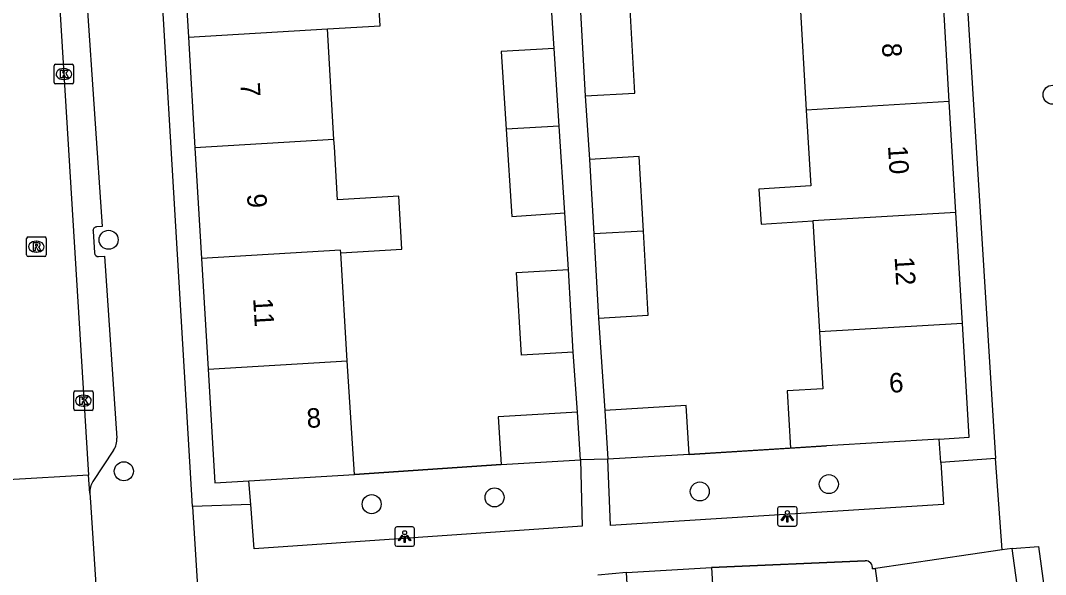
# Model space of a CAD drawing. Extents: x 159053 to 160041, y 380450 to 381422.
# Drawn here: x 159617.1 to 159669.8, y 381129.1 to 381157.6 of the extents above; entities that cross this region are included whole.
import ezdxf

# ---------------------------------------------------------------- set-up
doc = ezdxf.new("R2010")
doc.units = 0
for name, color, linetype in [('IMGEO_Boom', 7, 'Continuous'), ('IMGEO_Groenvoorziening', 7, 'Continuous'), ('IMGEO_Kolk', 7, 'Continuous'), ('IMGEO_Lichtpunt', 7, 'Continuous'), ('IMGEO_Muur', 7, 'Continuous'), ('IMGEO_Pand', 7, 'Continuous'), ('IMGEO_Pand_nummerreeks', 7, 'Continuous'), ('IMGEO_Rijbaan_lokaal_open', 7, 'Continuous'), ('IMGEO_Rioolput', 7, 'Continuous'), ('IMGEO_Voetpad_open', 7, 'Continuous')]:
    doc.layers.add(name, color=color, linetype=linetype)

msp = doc.modelspace()

# ---------------------------------------------------------------- linework, layer by layer
at = {"layer": 'IMGEO_Boom'}
for centre in [(159670.128, 381153.776), (159621.666, 381146.323), (159622.448, 381134.43), (159658.638, 381133.772), (159652.014, 381133.396), (159635.17, 381132.742), (159641.478, 381133.09)]:
    msp.add_circle(centre, 0.489, dxfattribs=at)
at = {"layer": 'IMGEO_Groenvoorziening'}
for points in [[(159664.387, 381134.882), (159664.307, 381136.089)], [(159656.669, 381135.627), (159651.462, 381135.295)], [(159634.284, 381134.272), (159641.811, 381134.775)], [(159628.96, 381132.732), (159628.867, 381133.949)]]:
    msp.add_lwpolyline(points, dxfattribs=at)
at = {"layer": 'IMGEO_Kolk'}
for p, q in [((159618.945, 381155.337), (159619.797, 381155.337)), ((159618.87, 381154.411), (159618.87, 381155.263)), ((159619.358, 381155.117), (159619.383, 381155.117)), ((159619.871, 381155.263), (159619.871, 381154.411)), ((159619.797, 381154.337), (159618.945, 381154.337)), ((159619.381, 381154.557), (159619.356, 381154.557)), ((159619.873, 381137.634), (159619.873, 381138.486)), ((159619.948, 381138.56), (159620.8, 381138.56)), ((159620.874, 381138.486), (159620.874, 381137.634)), ((159620.361, 381138.34), (159620.386, 381138.34)), ((159620.8, 381137.56), (159619.948, 381137.56)), ((159620.384, 381137.78), (159620.359, 381137.78))]:
    msp.add_line(p, q, dxfattribs=at)
for points in [[(159618.945, 381155.337), (159619.797, 381155.337)], [(159618.87, 381154.411), (159618.87, 381155.263)], [(159619.191, 381155.037), (159619.314, 381155.037), (159619.314, 381154.886), (159619.444, 381155.037), (159619.608, 381155.037), (159619.462, 381154.886), (159619.615, 381154.637), (159619.463, 381154.637), (159619.378, 381154.801), (159619.314, 381154.734), (159619.314, 381154.637), (159619.191, 381154.637), (159619.191, 381155.037)], [(159619.871, 381155.263), (159619.871, 381154.411)], [(159619.797, 381154.337), (159618.945, 381154.337)], [(159619.873, 381137.634), (159619.873, 381138.486)], [(159619.948, 381138.56), (159620.8, 381138.56)], [(159620.874, 381138.486), (159620.874, 381137.634)], [(159620.194, 381138.26), (159620.317, 381138.26), (159620.317, 381138.109), (159620.447, 381138.26), (159620.611, 381138.26), (159620.465, 381138.109), (159620.618, 381137.86), (159620.466, 381137.86), (159620.381, 381138.024), (159620.317, 381137.957), (159620.317, 381137.86), (159620.194, 381137.86), (159620.194, 381138.26)], [(159620.8, 381137.56), (159619.948, 381137.56)]]:
    msp.add_lwpolyline(points, dxfattribs=at)
for centre, start, end in [((159618.947, 381155.261), 91.552, 178.448), ((159618.947, 381155.261), 91.552, 178.448), ((159619.795, 381155.261), 1.552, 88.448), ((159619.795, 381155.261), 1.552, 88.448), ((159618.947, 381154.413), 181.552, 268.448), ((159618.947, 381154.413), 181.552, 268.448), ((159619.795, 381154.413), 271.552, 358.448), ((159619.795, 381154.413), 271.552, 358.448), ((159619.95, 381138.484), 91.552, 178.448), ((159619.95, 381138.484), 91.552, 178.448), ((159620.798, 381138.484), 1.552, 88.448), ((159620.798, 381138.484), 1.552, 88.448), ((159619.95, 381137.636), 181.552, 268.448), ((159619.95, 381137.636), 181.552, 268.448), ((159620.798, 381137.636), 271.552, 358.448), ((159620.798, 381137.636), 271.552, 358.448)]:
    msp.add_arc(centre, 0.0765, start, end, dxfattribs=at)
for centre, major_axis, ratio, start_param, end_param in [((159619.357, 381154.837), (-0.387, 0.002), 0.722429, 4.712389, 7.853982), ((159619.382, 381154.837), (-0.39, 0.002), 0.717154, 1.570796, 4.712389), ((159620.36, 381138.06), (-0.387, 0.002), 0.722429, 4.712389, 7.853982), ((159620.385, 381138.06), (-0.39, 0.002), 0.717154, 1.570796, 4.712389)]:
    msp.add_ellipse(centre, major_axis=major_axis, ratio=ratio, start_param=start_param, end_param=end_param, dxfattribs=at)
at = {"layer": 'IMGEO_Lichtpunt'}
for p, q in [((159656.01, 381132.519), (159656.01, 381131.712)), ((159656.01, 381132.519), (159656.01, 381131.712)), ((159656.912, 381132.614), (159656.104, 381132.614)), ((159656.912, 381132.614), (159656.104, 381132.614)), ((159657.006, 381131.712), (159657.006, 381132.519)), ((159657.006, 381131.712), (159657.006, 381132.519)), ((159636.365, 381131.479), (159636.365, 381130.672)), ((159636.365, 381131.479), (159636.365, 381130.672)), ((159637.267, 381131.574), (159636.459, 381131.574)), ((159637.267, 381131.574), (159636.459, 381131.574)), ((159637.361, 381130.672), (159637.361, 381131.479)), ((159637.361, 381130.672), (159637.361, 381131.479)), ((159656.104, 381131.618), (159656.912, 381131.618)), ((159656.104, 381131.618), (159656.912, 381131.618)), ((159636.459, 381130.578), (159637.267, 381130.578)), ((159636.459, 381130.578), (159637.267, 381130.578))]:
    msp.add_line(p, q, dxfattribs=at)
for points in [[(159656.384, 381132.183), (159656.423, 381132.155), (159656.235, 381131.893), (159656.197, 381131.92), (159656.384, 381132.183)], [(159656.596, 381132.155), (159656.634, 381132.182), (159656.821, 381131.92), (159656.782, 381131.892), (159656.596, 381132.155)], [(159656.486, 381132.135), (159656.533, 381132.135), (159656.533, 381131.813), (159656.486, 381131.813), (159656.486, 381132.135)], [(159636.739, 381131.143), (159636.778, 381131.115), (159636.59, 381130.853), (159636.552, 381130.88), (159636.739, 381131.143)], [(159636.951, 381131.115), (159636.989, 381131.142), (159637.176, 381130.88), (159637.137, 381130.852), (159636.951, 381131.115)], [(159636.841, 381131.095), (159636.888, 381131.095), (159636.888, 381130.773), (159636.841, 381130.773), (159636.841, 381131.095)]]:
    msp.add_lwpolyline(points, dxfattribs=at)
for centre in [(159656.509, 381132.317), (159636.864, 381131.277)]:
    msp.add_circle(centre, 0.0994, dxfattribs=at)
for centre, start, end in [((159656.104, 381132.519), 90, 180), ((159656.104, 381132.519), 90, 180), ((159656.912, 381132.519), 0, 90), ((159656.912, 381132.519), 0, 90), ((159656.104, 381131.712), 180, 270), ((159656.104, 381131.712), 180, 270), ((159656.912, 381131.712), 270, 0), ((159656.912, 381131.712), 270, 360), ((159636.459, 381131.479), 90, 180), ((159636.459, 381131.479), 90, 180), ((159637.267, 381131.479), 0, 90), ((159637.267, 381131.479), 0, 90), ((159636.459, 381130.672), 180, 270), ((159636.459, 381130.672), 180, 270), ((159637.267, 381130.672), 270, 0), ((159637.267, 381130.672), 270, 360)]:
    msp.add_arc(centre, 0.0946, start, end, dxfattribs=at)
at = {"layer": 'IMGEO_Muur'}
for points in [[(159651.462, 381135.295), (159658.51, 381135.744)], [(159641.811, 381134.775), (159634.284, 381134.272)], [(159652.616, 381129.495), (159660.501, 381129.836)], [(159660.884, 381129.414), (159661.027, 381129.435)]]:
    msp.add_lwpolyline(points, dxfattribs=at)
msp.add_arc((159660.515, 381129.464), 0.372, 352.2658, 92.1869, dxfattribs=at)
at = {"layer": 'IMGEO_Pand'}
for points in [[(159632.896, 381157.16), (159635.606, 381157.321), (159635.267, 381163.006), (159632.557, 381162.845)], [(159625.422, 381162.42), (159625.761, 381156.735)], [(159664.823, 381153.421), (159664.484, 381159.118)], [(159657.144, 381158.683), (159657.483, 381152.986)], [(159645.89, 381158.016), (159646.131, 381153.714)], [(159646.131, 381153.714), (159648.687, 381153.857), (159648.446, 381158.168)], [(159625.761, 381156.735), (159632.896, 381157.16)], [(159633.235, 381151.475), (159632.896, 381157.16)], [(159625.761, 381156.735), (159626.1, 381151.05)], [(159644.535, 381156.153), (159641.823, 381155.991), (159642.079, 381152.002)], [(159644.792, 381152.163), (159644.535, 381156.153)], [(159664.823, 381153.421), (159657.483, 381152.986)], [(159665.162, 381147.724), (159664.823, 381153.421)], [(159657.483, 381152.986), (159657.715, 381149.088), (159655.053, 381148.93), (159655.16, 381147.131), (159657.823, 381147.289)], [(159644.792, 381152.163), (159642.079, 381152.002)], [(159645.079, 381147.7), (159644.792, 381152.163)], [(159642.079, 381152.002), (159642.368, 381147.525), (159645.079, 381147.7)], [(159633.235, 381151.475), (159626.1, 381151.05)], [(159633.581, 381145.657), (159636.725, 381145.845), (159636.564, 381148.567), (159633.419, 381148.38), (159633.257, 381151.103), (159633.235, 381151.475)], [(159626.1, 381151.05), (159626.439, 381145.365)], [(159649.123, 381146.773), (159648.91, 381150.595), (159646.353, 381150.452)], [(159646.353, 381150.452), (159646.568, 381146.622)], [(159665.162, 381147.724), (159657.823, 381147.289)], [(159665.502, 381142.027), (159665.162, 381147.724)], [(159657.823, 381147.289), (159658.162, 381141.592)], [(159649.123, 381146.773), (159646.568, 381146.622)], [(159646.568, 381146.622), (159646.809, 381142.305)], [(159646.809, 381142.305), (159649.365, 381142.448), (159649.123, 381146.773)], [(159633.581, 381145.657), (159633.573, 381145.79), (159626.439, 381145.365)], [(159626.439, 381145.365), (159626.777, 381139.68)], [(159633.912, 381140.105), (159633.581, 381145.657)], [(159645.519, 381140.557), (159642.854, 381140.398), (159642.602, 381144.635), (159645.267, 381144.793)], [(159645.519, 381140.557), (159645.267, 381144.793)], [(159665.502, 381142.027), (159658.162, 381141.592)], [(159664.307, 381136.089), (159665.85, 381136.181), (159665.502, 381142.027)], [(159658.162, 381141.592), (159658.336, 381138.668), (159656.495, 381138.558), (159656.669, 381135.627)], [(159626.777, 381139.68), (159633.912, 381140.105)], [(159634.284, 381134.272), (159633.912, 381140.105)], [(159626.777, 381139.68), (159627.125, 381133.845), (159628.867, 381133.949)], [(159645.738, 381137.468), (159641.665, 381137.225), (159641.811, 381134.775)], [(159645.885, 381135.017), (159645.738, 381137.468)], [(159651.462, 381135.295), (159651.313, 381137.804), (159647.136, 381137.555)], [(159647.136, 381137.555), (159647.285, 381135.046)], [(159664.307, 381136.089), (159658.51, 381135.744), (159656.669, 381135.627)], [(159641.811, 381134.775), (159645.885, 381135.017)], [(159651.462, 381135.295), (159647.285, 381135.046)], [(159628.867, 381133.949), (159634.284, 381134.272)], [(159667.53, 381130.39), (159661.027, 381129.435)], [(159668.05, 381130.466), (159667.53, 381130.39)], [(159668.849, 381124.614), (159668.05, 381130.466)], [(159648.258, 381129.236), (159652.616, 381129.495)], [(159648.414, 381126.627), (159648.258, 381129.236)], [(159652.616, 381129.495), (159652.772, 381126.886), (159648.414, 381126.627)], [(159661.826, 381123.579), (159661.703, 381124.481), (159661.027, 381129.435)]]:
    msp.add_lwpolyline(points, dxfattribs=at)
at = {"layer": 'IMGEO_Rijbaan_lokaal_open'}
for points in [[(159618.267, 381172.995), (159618.959, 381161.536), (159620.639, 381134.237)], [(159620.639, 381134.237), (159616.518, 381133.993)], [(159620.696, 381133.307), (159620.639, 381134.237)], [(159620.696, 381133.307), (159620.73, 381132.839), (159621.044, 381128.068), (159621.135, 381127.424)]]:
    msp.add_lwpolyline(points, dxfattribs=at)
at = {"layer": 'IMGEO_Rioolput'}
for p, q in [((159617.459, 381145.542), (159617.459, 381146.394)), ((159617.534, 381146.468), (159618.386, 381146.468)), ((159618.46, 381146.394), (159618.46, 381145.542)), ((159617.947, 381146.248), (159617.972, 381146.248)), ((159618.386, 381145.468), (159617.534, 381145.468)), ((159617.97, 381145.688), (159617.945, 381145.688))]:
    msp.add_line(p, q, dxfattribs=at)
for points in [[(159617.459, 381145.542), (159617.459, 381146.394)], [(159617.534, 381146.468), (159618.386, 381146.468)], [(159618.46, 381146.394), (159618.46, 381145.542)], [(159618.048, 381146.166), (159617.796, 381146.168), (159617.796, 381145.768)], [(159617.796, 381145.768), (159617.92, 381145.768), (159617.92, 381145.93), (159617.931, 381145.93)], [(159617.974, 381146.087), (159617.92, 381146.087), (159617.92, 381146.006)], [(159617.92, 381146.006), (159617.972, 381146.006)], [(159617.978, 381145.901), (159618.049, 381145.768), (159618.189, 381145.768), (159618.124, 381145.894)], [(159618.386, 381145.468), (159617.534, 381145.468)]]:
    msp.add_lwpolyline(points, dxfattribs=at)
for centre, radius, start, end in [((159617.536, 381146.392), 0.0765, 91.552, 178.448), ((159617.536, 381146.392), 0.0765, 91.552, 178.448), ((159618.384, 381146.392), 0.0765, 1.552, 88.448), ((159618.384, 381146.392), 0.0765, 1.552, 88.448), ((159617.93, 381145.877), 0.0533, 26.0293, 88.6989), ((159617.956, 381146.195), 0.19, 274.7715, 282.9687), ((159617.98, 381145.991), 0.0964, 77.0061, 93.1865), ((159617.994, 381146.048), 0.0378, 276.6634, 79.6772), ((159618.047, 381146.056), 0.109, 350.3612, 89.416), ((159618.045, 381146.056), 0.112, 277.5842, 350.9817), ((159618.029, 381145.841), 0.108, 29.5134, 73.7905), ((159617.536, 381145.544), 0.0765, 181.552, 268.448), ((159617.536, 381145.544), 0.0765, 181.552, 268.448), ((159618.384, 381145.544), 0.0765, 271.552, 358.448), ((159618.384, 381145.544), 0.0765, 271.552, 358.448)]:
    msp.add_arc(centre, radius, start, end, dxfattribs=at)
for centre, major_axis, ratio, start_param, end_param in [((159617.946, 381145.968), (-0.387, 0.002), 0.722429, 4.712389, 7.853982), ((159617.971, 381145.968), (-0.39, 0.002), 0.717154, 1.570796, 4.712389)]:
    msp.add_ellipse(centre, major_axis=major_axis, ratio=ratio, start_param=start_param, end_param=end_param, dxfattribs=at)
at = {"layer": 'IMGEO_Voetpad_open'}
for points in [[(159664.635, 381176.427), (159667.199, 381135.088)], [(159625.978, 381132.627), (159623.525, 381173.81)], [(159644.535, 381156.153), (159644.315, 381159.567)], [(159620.26, 381158.557), (159620.553, 381158.577), (159621.343, 381147.003), (159621.05, 381146.983)], [(159646.131, 381153.714), (159646.353, 381150.452)], [(159645.267, 381144.793), (159645.079, 381147.7)], [(159620.865, 381146.77), (159620.941, 381145.645)], [(159621.154, 381145.459), (159621.447, 381145.479), (159622.085, 381136.137)], [(159646.809, 381142.305), (159647.136, 381137.555)], [(159645.738, 381137.468), (159645.519, 381140.557)], [(159621.922, 381135.518), (159620.861, 381133.911)], [(159645.885, 381135.017), (159645.982, 381131.605), (159629.132, 381130.442), (159628.96, 381132.732)], [(159647.285, 381135.046), (159645.885, 381135.017)], [(159664.387, 381134.882), (159664.53, 381132.721), (159647.423, 381131.643), (159647.285, 381135.046)], [(159667.199, 381135.088), (159664.387, 381134.882)], [(159667.53, 381130.39), (159667.199, 381135.088)], [(159628.96, 381132.732), (159625.978, 381132.627)], [(159625.978, 381132.627), (159626.32, 381127.125)], [(159668.05, 381130.466), (159669.393, 381130.571), (159683.353, 381027.651)], [(159660.501, 381129.836), (159652.616, 381129.495)], [(159648.258, 381129.236), (159646.785, 381129.095)], [(159661.027, 381129.435), (159660.884, 381129.414)]]:
    msp.add_lwpolyline(points, dxfattribs=at)
for centre, radius, start, end in [((159621.063, 381146.785), 0.199, 93.7381, 184.3104), ((159621.141, 381145.659), 0.2, 183.9405, 273.802), ((159621.081, 381136.07), 1.006, 326.6952, 3.7994), ((159621.696, 381133.358), 1.001, 146.4971, 182.9445), ((159660.515, 381129.464), 0.372, 352.2658, 92.1869)]:
    msp.add_arc(centre, radius, start, end, dxfattribs=at)

# ---------------------------------------------------------------- texts
at = {"layer": 'IMGEO_Pand_nummerreeks'}
for s, rotation, p in [('8', 273.4089, (159661.36, 381156.405)), ('7', 273.4098, (159628.427, 381154.379)), ('10', 273.4089, (159661.673, 381151.144)), ('9', 273.4089, (159628.767, 381148.67)), ('12', 273.4089, (159662.013, 381145.429)), ('11', 273.4089, (159629.085, 381143.306)), ('6', 3.4091, (159661.756, 381138.462)), ('8', 3.4108, (159631.855, 381136.652))]:
    msp.add_text(s, height=1, rotation=rotation, dxfattribs=at).set_placement(p)

doc.saveas('drawing.dxf')
